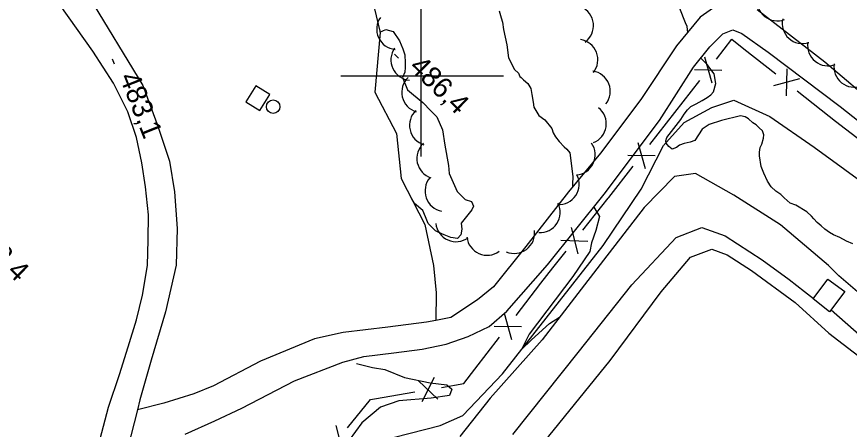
# Model space of a CAD drawing. Extents: x 642515 to 647219, y 6080136 to 6084356.
# Drawn here: x 642940.4 to 643063.2, y 6082547.9 to 6082608.8 of the extents above; entities that cross this region are included whole.
import ezdxf

# ---------------------------------------------------------------- set-up
doc = ezdxf.new("R2010")
doc.units = 0
for name, color, linetype in [('Level 19', 7, 'Continuous'), ('Level 2', 7, 'Continuous'), ('Level 21', 7, 'Continuous'), ('Level 3', 7, 'Continuous'), ('Level 31', 7, 'Continuous'), ('Level 33', 7, 'Continuous'), ('Level 36', 7, 'Continuous'), ('Level 37', 7, 'Continuous'), ('Level 4', 7, 'Continuous'), ('Level 44', 7, 'Continuous'), ('Level 54', 7, 'Continuous'), ('Level 61', 7, 'Continuous')]:
    doc.layers.add(name, color=color, linetype=linetype)

msp = doc.modelspace()

# ---------------------------------------------------------------- linework, layer by layer
at = {"layer": 'Level 19'}
for points in [[(643044.77, 6082611.27), (643041.2, 6082608.69), (643037.7, 6082604.45), (643032.44, 6082596.54), (643026.5, 6082588.64), (643021.78, 6082582.96), (643015.49, 6082574.86), (643010.71, 6082568.94), (643008.34, 6082567), (643004.39, 6082564.41), (643002.2, 6082563.98), (643000.81, 6082563.7), (642995.12, 6082562.97), (642988.54, 6082562.2), (642984.29, 6082561.26), (642976.31, 6082557.99), (642969.38, 6082554.32), (642966.48, 6082553.16), (642962.05, 6082551.77), (642958.17, 6082550.8)], [(643067.57, 6082595.3), (643059.59, 6082602.07), (643049.59, 6082609.8)], [(642965.22, 6082547.21), (642969.61, 6082549.16), (642973.6, 6082551.02), (642981.33, 6082555.05), (642988.48, 6082557.84), (642991.56, 6082558.68), (642996, 6082559.22), (643000.19, 6082559.76), (643003.73, 6082560.5), (643006.96, 6082561.59), (643010.08, 6082563.09), (643012.67, 6082565.36), (643018.66, 6082572.19), (643027.01, 6082582.59), (643035.18, 6082593.48), (643040.22, 6082601.33), (643042.62, 6082604.34), (643044.55, 6082606.23), (643046.03, 6082606.83), (643047.32, 6082606.28), (643051.23, 6082603.55), (643061.82, 6082595.52), (643077.46, 6082583.19)], [(643065.76, 6082567), (643061.65, 6082570.54), (643060.12, 6082572.09), (643060.13, 6082572.1), (643053.06, 6082578.07), (643046.15, 6082582.43), (643040.52, 6082585.66), (643037.42, 6082585.22), (643032.94, 6082580.64), (643026.92, 6082572.85), (643017.86, 6082561.12), (643010.22, 6082552.49), (643005.72, 6082546.87)], [(643013.57, 6082547.18), (643023.19, 6082559.25), (643031.12, 6082569.23), (643037.63, 6082576.2), (643041.44, 6082577.68), (643044.87, 6082576.45), (643050.32, 6082572.93), (643054.31, 6082570.03), (643056.59, 6082568.22), (643057.89, 6082567.22)], [(643060.51, 6082565.56), (643065.05, 6082561.56)]]:
    msp.add_lwpolyline(points, dxfattribs=at)
at = {"layer": 'Level 2'}
for points in [[(643011.52, 6082609.64), (643011.81, 6082608.61), (643012.01, 6082607.98), (643012.18, 6082606.9), (643012.66, 6082604.62), (643012.92, 6082602.7), (643013.82, 6082600.97), (643014.41, 6082600.44), (643014.6, 6082599.96), (643014.77, 6082599.81), (643015.15, 6082599.47), (643015.79, 6082598.9), (643016.23, 6082598.19), (643016.35, 6082597.31), (643016.53, 6082596.15), (643016.65, 6082595.43), (643017.4, 6082594.22), (643018.29, 6082593.58), (643019.32, 6082592.26), (643019.52, 6082591.63), (643019.83, 6082591.04), (643020.39, 6082590.38), (643021.12, 6082589.57), (643021.5, 6082589.23), (643021.94, 6082588.69), (643022.39, 6082585.21), (643022.37, 6082584.08), (643022.35, 6082583.65)], [(643039.36, 6082606.46), (643039.25, 6082607.34), (643039.02, 6082607.85), (643038.18, 6082609.99)], [(642993.96, 6082606.51), (642994.8, 6082606.87), (642995.92, 6082606.6), (642996.85, 6082605.23), (642997.32, 6082604.02), (642997.63, 6082603.16), (642997.65, 6082601.95), (642997.67, 6082601.26), (642997.61, 6082600.57), (642997.27, 6082599.82), (642998.03, 6082597.99), (642998.91, 6082597.25), (643000.26, 6082596.12), (643001.46, 6082594.89), (643002.35, 6082594), (643003.2, 6082592.09), (643003.52, 6082589.82), (643004.05, 6082586.84), (643004.16, 6082585.64), (643005.35, 6082583), (643006.51, 6082581.81), (643007.47, 6082581.53), (643007.77, 6082580.83), (643007.53, 6082580.28), (643005.95, 6082578.34), (643006.03, 6082577.46), (643005.9, 6082576.6), (643005.38, 6082576.07), (643004.39, 6082576.23), (643003.42, 6082576.59), (643002.66, 6082576.93), (643002.15, 6082577.21), (643001.05, 6082578.29), (643000.68, 6082579.26), (643000.28, 6082580.2), (642999.05, 6082581.22), (642998.64, 6082581.92)], [(643057.62, 6082579.37), (643056.94, 6082579.98), (643055.3, 6082580.99), (643054.48, 6082581.27), (643053.58, 6082582.07), (643053.07, 6082582.53), (643052.36, 6082583.02), (643051.64, 6082583.67), (643051.11, 6082584.53), (643050.6, 6082585.67), (643050.19, 6082586.66), (643049.95, 6082588.26), (643049.96, 6082588.79), (643050.05, 6082589.48), (643050.27, 6082589.97), (643050.55, 6082590.87), (643050.6, 6082591.36), (643050.37, 6082591.95), (643049.9, 6082592.37), (643049.47, 6082592.84), (643048.97, 6082593.14), (643048.33, 6082593.71), (643047.83, 6082594.01), (643047.13, 6082594.17), (643044.33, 6082593.47), (643042.53, 6082592.85), (643041.46, 6082592.19), (643040.41, 6082590.53), (643039.69, 6082590.25), (643038.85, 6082590.09), (643038.13, 6082589.81), (643037.7, 6082589.5), (643037.06, 6082589.23), (643036.56, 6082589.61), (643036.17, 6082590.11), (643036.11, 6082590.47), (643036.25, 6082590.96), (643038.35, 6082593.61), (643038.84, 6082594.4), (643039.33, 6082595.03), (643039.79, 6082595.54), (643040.59, 6082595.9), (643041.5, 6082596.39), (643042.21, 6082596.83), (643042.76, 6082597.26), (643043.14, 6082597.69), (643043.49, 6082598.91), (643043.25, 6082600.35), (643042.47, 6082601.36), (643042.29, 6082601.68), (643041.29, 6082602.67)], [(643025.49, 6082580.7), (643026.34, 6082579.28), (643025.79, 6082577.24), (643025.15, 6082575.44), (643024.89, 6082574.14), (643022.4, 6082570.47), (643015.94, 6082561.93), (643014.84, 6082559.69), (643016.31, 6082561.14), (643018.94, 6082563.52), (643020.44, 6082564.48), (643020.45, 6082564.48)], [(643063.71, 6082575.28), (643062.75, 6082575.67), (643061.79, 6082576.23), (643060.88, 6082576.59), (643060.29, 6082576.96), (643059.58, 6082577.45), (643059.03, 6082577.95), (643058.47, 6082578.44), (643057.96, 6082578.98), (643057.62, 6082579.37)], [(642990.49, 6082557.65), (642992.86, 6082557.05), (642994.66, 6082556.74), (642997.59, 6082555.56), (643001.36, 6082554.78), (643003.8, 6082554.5), (643004.56, 6082553.82), (643004.2, 6082552.92), (643001.51, 6082552.5), (642996.76, 6082552.1), (642994.01, 6082551.2), (642991.29, 6082548.89), (642988.49, 6082545.06)]]:
    msp.add_lwpolyline(points, dxfattribs=at)
at = {"layer": 'Level 21'}
for points in [[(642950.94, 6082611.83), (642958.97, 6082598.64), (642961.2, 6082592.65), (642962.89, 6082587.46), (642963.65, 6082582.94), (642964.05, 6082577.52), (642963.88, 6082572.15), (642962.33, 6082565.26), (642960.23, 6082558.1), (642958.54, 6082552.26), (642958.17, 6082550.8), (642956.24, 6082543.15), (642953.42, 6082532.97), (642950.26, 6082520.5), (642947.97, 6082509.7), (642945.87, 6082498.58), (642944.78, 6082483.96), (642943.65, 6082471.53), (642943.65, 6082471.49), (642943.44, 6082463.69), (642943.35, 6082460.19), (642943.54, 6082448.73), (642943.64, 6082442.35)], [(642952.68, 6082546.53), (642953.9, 6082551.17), (642955.53, 6082555.99), (642956.79, 6082560.07), (642958.06, 6082564.06), (642958.91, 6082567.68), (642959.67, 6082572.06), (642959.77, 6082575.88), (642959.8, 6082579.53), (642959.39, 6082583.66), (642958.85, 6082587.21), (642958.02, 6082590.95), (642956.78, 6082594.75), (642954.66, 6082598.95), (642951.6, 6082603.68), (642946.76, 6082610.48)]]:
    msp.add_lwpolyline(points, dxfattribs=at)
at = {"layer": 'Level 3'}
for p, q in [((642996.1, 6082603.23), (642996.67, 6082602.67)), ((642954.47, 6082602.57), (642954.76, 6082601.82))]:
    msp.add_line(p, q, dxfattribs=at)
at = {"layer": 'Level 31'}
for points in [[(642974.18, 6082596.2), (642976.23, 6082594.94), (642977.69, 6082597.3), (642975.64, 6082598.57), (642974.18, 6082596.2)], [(643057.85, 6082567.17), (643060.02, 6082570.08), (643062.52, 6082568.22), (643060.28, 6082565.25), (643057.85, 6082567.17)]]:
    msp.add_lwpolyline(points, dxfattribs=at)
at = {"layer": 'Level 33'}
msp.add_lwpolyline([(643020.59, 6082528.2), (643017.52, 6082530.42), (643015.08, 6082532.92), (643013.93, 6082535.72), (643013.92, 6082539.1), (643015.54, 6082542.4), (643018.88, 6082546.92), (643027.9, 6082558.09), (643035.43, 6082568.21), (643039.76, 6082573.31), (643042.9, 6082574.47), (643045.18, 6082573.66), (643048.78, 6082571.34), (643055.22, 6082566.63), (643060.15, 6082562.12), (643065.88, 6082557.74)], dxfattribs=at)
at = {"layer": 'Level 36'}
msp.add_circle((642978.2, 6082595.5), 1, dxfattribs=at)
at = {"layer": 'Level 37'}
for p, q in [((643047.65, 6082604.04), (643052.36, 6082600.32)), ((643041.83, 6082602.87), (643042.89, 6082599.01)), ((643040.36, 6082600.97), (643044.36, 6082600.9)), ((643053.97, 6082601.08), (643053.87, 6082597.08)), ((643055.85, 6082599.59), (643051.99, 6082598.56)), ((643037.45, 6082594.63), (643041.13, 6082599.37)), ((643055.49, 6082597.84), (643060.2, 6082594.12)), ((643033.76, 6082589.9), (643037.45, 6082594.63)), ((643032.01, 6082590.24), (643033.06, 6082586.38)), ((643030.53, 6082588.35), (643034.53, 6082588.28)), ((643023.89, 6082577.31), (643027.62, 6082582.01)), ((643022.14, 6082577.67), (643023.15, 6082573.8)), ((643020.64, 6082575.79), (643024.64, 6082575.68)), ((643014.04, 6082564.69), (643017.7, 6082569.45)), ((643012.29, 6082565.03), (643013.36, 6082561.18)), ((643010.82, 6082563.13), (643014.82, 6082563.08)), ((643007.94, 6082556.77), (643011.6, 6082561.52)), ((643001.97, 6082555.54), (643000.14, 6082551.99)), ((642999.6, 6082555.14), (643002.5, 6082552.39)), ((642993.17, 6082552.43), (642999.08, 6082553.43)), ((642987.44, 6082548.5), (642988.43, 6082544.63))]:
    msp.add_line(p, q, dxfattribs=at)
for points in [[(643043.59, 6082602.53), (643045.85, 6082605.46), (643047.65, 6082604.04)], [(643060.2, 6082594.12), (643061.13, 6082593.38), (643064.94, 6082590.44)], [(643027.62, 6082582.01), (643027.71, 6082582.12), (643031.3, 6082586.74)], [(643017.7, 6082569.45), (643019.47, 6082571.75), (643021.4, 6082574.18)], [(643003.03, 6082554.11), (643006.33, 6082554.67), (643007.94, 6082556.77)], [(642989.19, 6082548.13), (642992.55, 6082552.32), (642993.17, 6082552.43)]]:
    msp.add_lwpolyline(points, dxfattribs=at)
at = {"layer": 'Level 4'}
msp.add_lwpolyline([(642990.47, 6082543.22), (642993.79, 6082546.18), (643002.85, 6082548.5), (643006.18, 6082549.96), (643012.01, 6082556.1), (643026.87, 6082575.02), (643032.49, 6082583.34), (643035.79, 6082589.76), (643038.85, 6082593.17), (643042.89, 6082595.4), (643046.17, 6082596.46), (643051.45, 6082594.03), (643058, 6082589.55), (643071.04, 6082580.02), (643082.29, 6082571.94), (643089.2, 6082566.67), (643096.12, 6082561.39), (643102.21, 6082557.18)], dxfattribs=at)
at = {"layer": 'Level 44'}
for centre, start, end in [((643052.56, 6082611.15), 171.0965, 291.0744), ((643022.45, 6082607.45), 306.141, 66.119), ((642996.47, 6082606.94), 144.7791, 264.7571), ((643056.29, 6082607.8), 167.6623, 287.6402), ((643023.1, 6082602.42), 321.4325, 81.4104), ((643060.04, 6082604.52), 171.0145, 290.9925), ((642998.57, 6082602.39), 144.7791, 264.7571), ((643024.93, 6082597.77), 321.4325, 81.4104), ((643063.92, 6082601.37), 171.0145, 290.9925), ((643000.17, 6082597.62), 133.2293, 253.2072), ((643001.31, 6082592.76), 133.2293, 253.2072), ((643024.34, 6082592.99), 291.5218, 51.4997), ((643002.39, 6082587.87), 132.1491, 252.127), ((643022.7, 6082588.42), 274.5931, 34.5711), ((643003.6, 6082583.06), 139.5383, 259.5163), ((643020.33, 6082584.08), 266.3523, 26.3302), ((643017.56, 6082579.92), 266.3523, 26.3302), ((643005.18, 6082578.59), 186.3416, 306.3196), ((643009.76, 6082576.59), 186.3416, 306.3196), ((643013.77, 6082576.86), 246.9422, 6.9202)]:
    msp.add_arc(centre, 3, start, end, dxfattribs=at)
at = {"layer": 'Level 54'}
msp.add_lwpolyline([(642993.11, 6082610.12), (642993.98, 6082606.42), (642993.19, 6082597.62), (642996.39, 6082591.54), (642997.1, 6082584.92), (643000.59, 6082578.12), (643001.84, 6082572.1), (643002.24, 6082568.07), (643002.2, 6082563.98)], dxfattribs=at)
at = {"layer": 'Level 61'}
for p, q in [((643000, 6082612.16), (643000, 6082588.16)), ((643012.16, 6082600), (642988.16, 6082600))]:
    msp.add_line(p, q, dxfattribs=at)

# ---------------------------------------------------------------- texts
at = {"layer": 'Level 3'}
for s, rotation, p in [('486,4', 315.59, (642998.13, 6082601.18)), ('483,1', 291.5817, (642955.49, 6082599.88)), ('488,4', 315.59, (642933.24, 6082576.51))]:
    msp.add_text(s, height=3, rotation=rotation, dxfattribs=at).set_placement(p)

doc.saveas('drawing.dxf')
